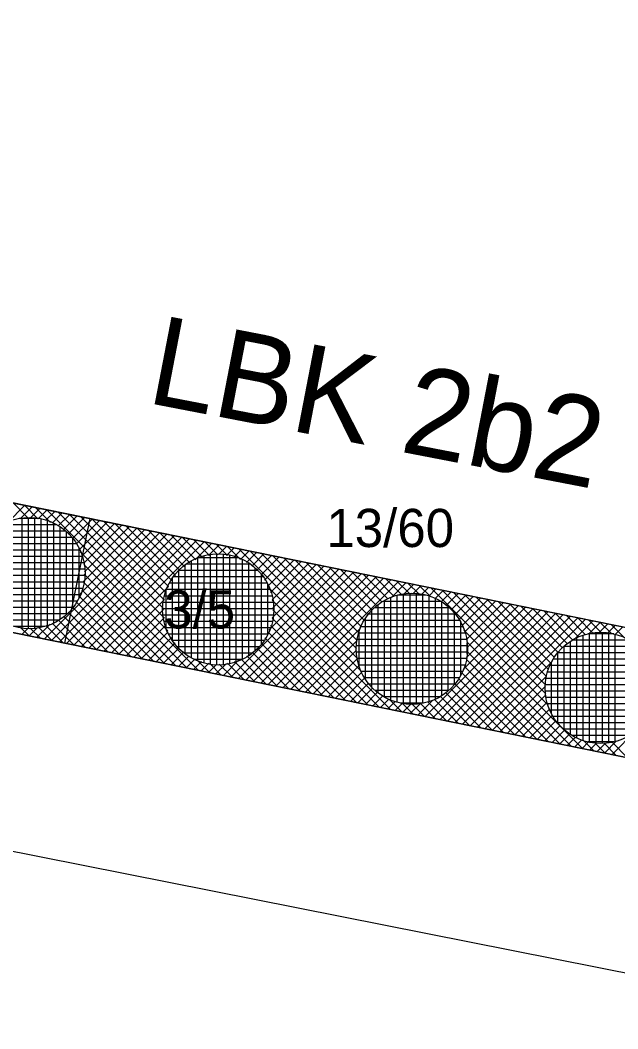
# Model space of a CAD drawing. Extents: x -566461 to -565198, y -1096301 to -1095707.
# Drawn here: x -565776.63 to -565757.83, y -1096136.49 to -1096104.77 of the extents above; entities that cross this region are included whole.
import ezdxf

# ---------------------------------------------------------------- set-up
doc = ezdxf.new("R2010")
doc.units = 0
for name, color, linetype in [('Vrstva 1', 7, 'Continuous'), ('Vrstva 40', 7, 'Continuous'), ('Vrstva 41', 7, 'Continuous'), ('Vrstva 42', 7, 'Continuous'), ('Vrstva 44', 7, 'Continuous')]:
    doc.layers.add(name, color=color, linetype=linetype)

msp = doc.modelspace()

# ---------------------------------------------------------------- linework, layer by layer
at = {"layer": 'Vrstva 1'}
for p, q in [((-565849.04, -1096105.26), (-565748.22, -1096125.78)), ((-565697.28, -1096140.23), (-565854, -1096108.33)), ((-565855.22, -1096115.35), (-565699.29, -1096146.31))]:
    msp.add_line(p, q, dxfattribs=at)
at = {"layer": 'Vrstva 41'}
for p, q in [((-565776.853, -1096119.953), (-565776.375, -1096120.432)), ((-565777.029, -1096120.574), (-565776.483, -1096120.028)), ((-565776.628, -1096120.456), (-565776.248, -1096120.076)), ((-565776.498, -1096120.025), (-565776.07, -1096120.453)), ((-565776.32, -1096120.431), (-565776.013, -1096120.124)), ((-565776.143, -1096120.098), (-565775.676, -1096120.565)), ((-565776.061, -1096120.455), (-565775.778, -1096120.172)), ((-565775.831, -1096120.508), (-565775.543, -1096120.22)), ((-565775.788, -1096120.17), (-565771.982, -1096123.976)), ((-565775.626, -1096120.585), (-565775.308, -1096120.268)), ((-565775.433, -1096120.242), (-565772.096, -1096123.579)), ((-565775.441, -1096120.684), (-565775.073, -1096120.315)), ((-565775.274, -1096120.799), (-565774.838, -1096120.363)), ((-565775.124, -1096120.932), (-565774.603, -1096120.411)), ((-565775.078, -1096120.314), (-565772.12, -1096123.273)), ((-565774.99, -1096121.081), (-565774.368, -1096120.459)), ((-565774.873, -1096121.247), (-565774.133, -1096120.507)), ((-565774.773, -1096121.43), (-565773.898, -1096120.555)), ((-565774.723, -1096120.387), (-565772.095, -1096123.014)), ((-565774.367, -1096120.459), (-565772.042, -1096122.785)), ((-565774.012, -1096120.531), (-565771.963, -1096122.581)), ((-565775.878, -1096124.232), (-565772.488, -1096120.842)), ((-565775.643, -1096124.279), (-565772.253, -1096120.889)), ((-565774.739, -1096122.81), (-565772.723, -1096120.794)), ((-565774.693, -1096121.632), (-565773.663, -1096120.602)), ((-565774.638, -1096121.86), (-565773.428, -1096120.65)), ((-565774.638, -1096122.426), (-565772.958, -1096120.746)), ((-565774.612, -1096122.117), (-565773.193, -1096120.698)), ((-565773.657, -1096120.604), (-565771.864, -1096122.397)), ((-565773.302, -1096120.676), (-565771.747, -1096122.231)), ((-565772.947, -1096120.748), (-565771.613, -1096122.082)), ((-565772.592, -1096120.82), (-565771.463, -1096121.949)), ((-565772.237, -1096120.893), (-565771.297, -1096121.832)), ((-565775.408, -1096124.327), (-565772.018, -1096120.937)), ((-565775.173, -1096124.375), (-565771.783, -1096120.985)), ((-565774.938, -1096124.423), (-565771.548, -1096121.033)), ((-565774.703, -1096124.471), (-565771.313, -1096121.081)), ((-565774.468, -1096124.519), (-565771.078, -1096121.129)), ((-565774.233, -1096124.566), (-565770.843, -1096121.176)), ((-565771.882, -1096120.965), (-565771.113, -1096121.734)), ((-565771.526, -1096121.037), (-565770.907, -1096121.656)), ((-565771.171, -1096121.11), (-565770.678, -1096121.603)), ((-565770.816, -1096121.182), (-565770.418, -1096121.58)), ((-565774.745, -1096121.496), (-565771.02, -1096125.22)), ((-565771.122, -1096121.738), (-565770.608, -1096121.224)), ((-565770.709, -1096121.608), (-565770.373, -1096121.272)), ((-565770.461, -1096121.254), (-565770.11, -1096121.605)), ((-565770.397, -1096121.579), (-565770.138, -1096121.32)), ((-565770.136, -1096121.601), (-565769.903, -1096121.368)), ((-565770.106, -1096121.326), (-565769.709, -1096121.724)), ((-565769.905, -1096121.653), (-565769.668, -1096121.416)), ((-565769.751, -1096121.399), (-565765.898, -1096125.251)), ((-565769.698, -1096121.728), (-565769.433, -1096121.463)), ((-565769.513, -1096121.826), (-565769.198, -1096121.511)), ((-565769.396, -1096121.471), (-565766.021, -1096124.846)), ((-565769.345, -1096121.942), (-565768.963, -1096121.559)), ((-565769.195, -1096122.074), (-565768.728, -1096121.607)), ((-565769.06, -1096122.222), (-565768.493, -1096121.655)), ((-565769.041, -1096121.543), (-565766.05, -1096124.534)), ((-565768.943, -1096122.387), (-565768.258, -1096121.703)), ((-565768.842, -1096122.57), (-565768.023, -1096121.75)), ((-565768.762, -1096122.772), (-565767.788, -1096121.798)), ((-565768.707, -1096123), (-565767.553, -1096121.846)), ((-565768.685, -1096121.616), (-565766.027, -1096124.274)), ((-565768.33, -1096121.688), (-565765.976, -1096124.042)), ((-565767.975, -1096121.76), (-565765.901, -1096123.834)), ((-565767.62, -1096121.832), (-565765.803, -1096123.649)), ((-565774.633, -1096121.89), (-565771.376, -1096125.148)), ((-565770.003, -1096125.427), (-565766.613, -1096122.037)), ((-565769.768, -1096125.475), (-565766.378, -1096122.085)), ((-565769.533, -1096125.523), (-565766.143, -1096122.133)), ((-565768.808, -1096123.95), (-565766.848, -1096121.99)), ((-565768.706, -1096123.565), (-565767.083, -1096121.942)), ((-565768.681, -1096123.257), (-565767.318, -1096121.894)), ((-565767.265, -1096121.905), (-565765.689, -1096123.481)), ((-565766.91, -1096121.977), (-565765.557, -1096123.33)), ((-565766.555, -1096122.049), (-565765.41, -1096123.194)), ((-565766.2, -1096122.122), (-565765.246, -1096123.075)), ((-565774.64, -1096122.449), (-565772.086, -1096125.003)), ((-565774.613, -1096122.193), (-565771.731, -1096125.076)), ((-565769.298, -1096125.571), (-565765.908, -1096122.181)), ((-565769.063, -1096125.619), (-565765.673, -1096122.229)), ((-565768.828, -1096125.667), (-565765.438, -1096122.277)), ((-565768.593, -1096125.714), (-565765.203, -1096122.324)), ((-565768.358, -1096125.762), (-565764.968, -1096122.372)), ((-565768.123, -1096125.81), (-565764.733, -1096122.42)), ((-565765.844, -1096122.194), (-565765.064, -1096122.974)), ((-565765.489, -1096122.266), (-565764.864, -1096122.891)), ((-565765.134, -1096122.338), (-565764.64, -1096122.833)), ((-565764.956, -1096122.926), (-565764.498, -1096122.468)), ((-565764.779, -1096122.411), (-565764.386, -1096122.804)), ((-565764.424, -1096122.483), (-565764.092, -1096122.815)), ((-565774.691, -1096122.681), (-565772.441, -1096124.931)), ((-565773.998, -1096124.614), (-565771.962, -1096122.578)), ((-565768.824, -1096122.609), (-565764.983, -1096126.449)), ((-565764.568, -1096122.821), (-565764.263, -1096122.516)), ((-565764.266, -1096122.802), (-565764.028, -1096122.564)), ((-565764.069, -1096122.555), (-565763.719, -1096122.905)), ((-565764.009, -1096122.828), (-565763.793, -1096122.611)), ((-565763.781, -1096122.883), (-565763.558, -1096122.659)), ((-565763.714, -1096122.628), (-565760.025, -1096126.316)), ((-565763.578, -1096122.962), (-565763.323, -1096122.707)), ((-565763.395, -1096123.062), (-565763.088, -1096122.755)), ((-565763.359, -1096122.7), (-565760.102, -1096125.956)), ((-565763.229, -1096123.179), (-565762.853, -1096122.803)), ((-565763.003, -1096122.772), (-565760.107, -1096125.668)), ((-565774.87, -1096123.068), (-565773.151, -1096124.787)), ((-565774.77, -1096122.885), (-565772.796, -1096124.859)), ((-565773.763, -1096124.662), (-565772.092, -1096122.991)), ((-565768.705, -1096123.01), (-565765.338, -1096126.377)), ((-565763.08, -1096123.313), (-565762.618, -1096122.851)), ((-565762.947, -1096123.462), (-565762.383, -1096122.898)), ((-565762.83, -1096123.629), (-565762.148, -1096122.946)), ((-565762.73, -1096123.812), (-565761.913, -1096122.994)), ((-565762.651, -1096124.016), (-565761.678, -1096123.042)), ((-565762.648, -1096122.844), (-565760.076, -1096125.416)), ((-565762.597, -1096124.244), (-565761.443, -1096123.09)), ((-565762.293, -1096122.917), (-565760.014, -1096125.196)), ((-565761.938, -1096122.989), (-565759.929, -1096124.998)), ((-565761.583, -1096123.061), (-565759.826, -1096124.818)), ((-565775.12, -1096123.384), (-565773.861, -1096124.642)), ((-565774.986, -1096123.234), (-565773.506, -1096124.714)), ((-565773.528, -1096124.71), (-565772.121, -1096123.303)), ((-565768.681, -1096123.317), (-565765.694, -1096126.305)), ((-565763.893, -1096126.671), (-565760.503, -1096123.281)), ((-565763.658, -1096126.719), (-565760.268, -1096123.329)), ((-565763.423, -1096126.767), (-565760.033, -1096123.377)), ((-565763.188, -1096126.815), (-565759.798, -1096123.425)), ((-565762.7, -1096125.196), (-565760.738, -1096123.233)), ((-565762.598, -1096124.811), (-565760.973, -1096123.185)), ((-565762.572, -1096124.502), (-565761.208, -1096123.138)), ((-565761.228, -1096123.134), (-565759.706, -1096124.655)), ((-565760.873, -1096123.206), (-565759.57, -1096124.509)), ((-565760.518, -1096123.278), (-565759.417, -1096124.379)), ((-565760.162, -1096123.35), (-565759.248, -1096124.265)), ((-565759.807, -1096123.423), (-565759.06, -1096124.17)), ((-565775.62, -1096123.732), (-565774.927, -1096124.425)), ((-565775.436, -1096123.633), (-565774.572, -1096124.497)), ((-565775.27, -1096123.517), (-565774.217, -1096124.57)), ((-565773.293, -1096124.758), (-565772.099, -1096123.564)), ((-565768.707, -1096123.574), (-565766.049, -1096126.232)), ((-565762.953, -1096126.862), (-565759.563, -1096123.472)), ((-565762.718, -1096126.91), (-565759.328, -1096123.52)), ((-565762.483, -1096126.958), (-565759.093, -1096123.568)), ((-565762.248, -1096127.006), (-565758.858, -1096123.616)), ((-565759.452, -1096123.495), (-565758.851, -1096124.097)), ((-565759.197, -1096124.239), (-565758.623, -1096123.664)), ((-565759.097, -1096123.567), (-565758.617, -1096124.047)), ((-565758.744, -1096124.068), (-565758.388, -1096123.712)), ((-565758.742, -1096123.64), (-565758.354, -1096124.028)), ((-565758.387, -1096123.712), (-565758.038, -1096124.06)), ((-565776.618, -1096123.865), (-565776.347, -1096124.136)), ((-565776.583, -1096124.088), (-565776.383, -1096123.888)), ((-565776.348, -1096124.136), (-565776.08, -1096123.868)), ((-565776.312, -1096123.889), (-565775.992, -1096124.208)), ((-565776.113, -1096124.184), (-565775.69, -1096123.761)), ((-565776.054, -1096123.864), (-565775.637, -1096124.281)), ((-565775.825, -1096123.81), (-565775.282, -1096124.353)), ((-565773.058, -1096124.806), (-565772.047, -1096123.795)), ((-565772.823, -1096124.853), (-565771.972, -1096124.002)), ((-565768.834, -1096124.013), (-565766.759, -1096126.088)), ((-565768.756, -1096123.807), (-565766.404, -1096126.16)), ((-565767.888, -1096125.858), (-565765.924, -1096123.894)), ((-565762.675, -1096123.949), (-565758.946, -1096127.678)), ((-565758.423, -1096124.03), (-565758.153, -1096123.759)), ((-565758.153, -1096124.042), (-565757.917, -1096123.807)), ((-565758.032, -1096123.784), (-565757.613, -1096124.202)), ((-565757.917, -1096124.089), (-565757.682, -1096123.855)), ((-565772.588, -1096124.901), (-565771.874, -1096124.187)), ((-565772.353, -1096124.949), (-565771.758, -1096124.355)), ((-565769.049, -1096124.363), (-565767.469, -1096125.943)), ((-565768.932, -1096124.197), (-565767.114, -1096126.015)), ((-565767.653, -1096125.906), (-565766.029, -1096124.282)), ((-565762.585, -1096124.322), (-565759.301, -1096127.606)), ((-565772.118, -1096124.997), (-565771.626, -1096124.505)), ((-565771.883, -1096125.045), (-565771.478, -1096124.64)), ((-565769.331, -1096124.647), (-565768.179, -1096125.799)), ((-565769.182, -1096124.513), (-565767.824, -1096125.871)), ((-565767.418, -1096125.954), (-565766.048, -1096124.584)), ((-565762.578, -1096124.612), (-565759.656, -1096127.533)), ((-565771.648, -1096125.093), (-565771.313, -1096124.757)), ((-565771.413, -1096125.14), (-565771.13, -1096124.858)), ((-565771.178, -1096125.188), (-565770.928, -1096124.938)), ((-565771.076, -1096124.882), (-565770.665, -1096125.293)), ((-565770.943, -1096125.236), (-565770.7, -1096124.993)), ((-565770.708, -1096125.284), (-565770.443, -1096125.019)), ((-565770.679, -1096124.996), (-565770.31, -1096125.365)), ((-565770.473, -1096125.332), (-565770.141, -1096124.999)), ((-565770.373, -1096125.02), (-565769.955, -1096125.437)), ((-565770.238, -1096125.38), (-565769.75, -1096124.892)), ((-565770.114, -1096124.995), (-565769.6, -1096125.509)), ((-565769.885, -1096124.942), (-565769.245, -1096125.582)), ((-565769.681, -1096124.863), (-565768.89, -1096125.654)), ((-565769.497, -1096124.764), (-565768.535, -1096125.726)), ((-565767.183, -1096126.001), (-565766.022, -1096124.841)), ((-565762.604, -1096124.868), (-565760.011, -1096127.461)), ((-565762.013, -1096127.054), (-565759.901, -1096124.943)), ((-565766.948, -1096126.049), (-565765.967, -1096125.069)), ((-565766.713, -1096126.097), (-565765.888, -1096125.272)), ((-565762.744, -1096125.294), (-565760.722, -1096127.317)), ((-565762.661, -1096125.094), (-565760.367, -1096127.389)), ((-565766.478, -1096126.145), (-565765.788, -1096125.455)), ((-565766.243, -1096126.193), (-565765.671, -1096125.621)), ((-565762.964, -1096125.64), (-565761.432, -1096127.172)), ((-565762.845, -1096125.476), (-565761.077, -1096127.244)), ((-565761.778, -1096127.102), (-565760.072, -1096125.396)), ((-565766.008, -1096126.241), (-565765.537, -1096125.77)), ((-565765.773, -1096126.288), (-565765.388, -1096125.903)), ((-565763.251, -1096125.919), (-565762.142, -1096127.027)), ((-565763.1, -1096125.787), (-565761.787, -1096127.1)), ((-565761.543, -1096127.15), (-565760.11, -1096125.717)), ((-565765.538, -1096126.336), (-565765.221, -1096126.02)), ((-565765.303, -1096126.384), (-565765.038, -1096126.12)), ((-565765.068, -1096126.432), (-565764.834, -1096126.199)), ((-565765.021, -1096126.128), (-565764.628, -1096126.521)), ((-565764.833, -1096126.48), (-565764.606, -1096126.253)), ((-565764.616, -1096126.251), (-565764.273, -1096126.594)), ((-565764.598, -1096126.528), (-565764.348, -1096126.278)), ((-565764.363, -1096126.575), (-565764.045, -1096126.258)), ((-565764.304, -1096126.28), (-565763.918, -1096126.666)), ((-565764.128, -1096126.623), (-565763.654, -1096126.15)), ((-565764.044, -1096126.257), (-565763.563, -1096126.738)), ((-565763.812, -1096126.206), (-565763.208, -1096126.811)), ((-565763.604, -1096126.131), (-565762.853, -1096126.883)), ((-565763.419, -1096126.033), (-565762.497, -1096126.955)), ((-565761.308, -1096127.197), (-565760.098, -1096125.987)), ((-565761.073, -1096127.245), (-565760.051, -1096126.223)), ((-565760.838, -1096127.293), (-565759.979, -1096126.435)), ((-565760.602, -1096127.341), (-565759.887, -1096126.625)), ((-565760.367, -1096127.389), (-565759.777, -1096126.798)), ((-565760.132, -1096127.437), (-565759.648, -1096126.953)), ((-565759.897, -1096127.484), (-565759.504, -1096127.091)), ((-565759.662, -1096127.532), (-565759.343, -1096127.213)), ((-565758.017, -1096127.867), (-565757.264, -1096127.113)), ((-565759.427, -1096127.58), (-565759.165, -1096127.318)), ((-565759.192, -1096127.628), (-565758.969, -1096127.405)), ((-565758.957, -1096127.676), (-565758.752, -1096127.47)), ((-565758.916, -1096127.425), (-565758.591, -1096127.75)), ((-565758.722, -1096127.724), (-565758.505, -1096127.506)), ((-565758.556, -1096127.502), (-565758.236, -1096127.823)), ((-565758.487, -1096127.771), (-565758.221, -1096127.505)), ((-565758.268, -1096127.507), (-565757.881, -1096127.895)), ((-565758.252, -1096127.819), (-565757.872, -1096127.439)), ((-565758.016, -1096127.476), (-565757.526, -1096127.967))]:
    msp.add_line(p, q, dxfattribs=at)
at = {"layer": 'Vrstva 42'}
msp.add_line((-565774.442, -1096120.443), (-565775.24, -1096124.361), dxfattribs=at)
msp.add_lwpolyline([(-565828.2, -1096027.12), (-565826.72, -1096023.51), (-565829.55, -1096025.32), (-565832.07, -1096026.09), (-565854, -1096108.33), (-565697.28, -1096140.23), (-565696.05, -1096136.4), (-565849.04, -1096105.26)], close=True, dxfattribs=at)
at = {"layer": 'Vrstva 44'}
for p, q in [((-565776.026, -1096120.44), (-565776.66, -1096120.44)), ((-565776.57, -1096123.894), (-565776.57, -1096120.427)), ((-565776.37, -1096123.909), (-565776.37, -1096120.412)), ((-565776.17, -1096123.9), (-565776.17, -1096120.419)), ((-565775.97, -1096123.868), (-565775.97, -1096120.45)), ((-565775.77, -1096123.813), (-565775.77, -1096120.507)), ((-565775.194, -1096120.84), (-565777.486, -1096120.84)), ((-565775.476, -1096120.64), (-565777.203, -1096120.64)), ((-565775.57, -1096123.731), (-565775.57, -1096120.591)), ((-565775.37, -1096123.614), (-565775.37, -1096120.703)), ((-565775.17, -1096123.461), (-565775.17, -1096120.861)), ((-565774.996, -1096121.04), (-565777.682, -1096121.04)), ((-565774.97, -1096123.246), (-565774.97, -1096121.074)), ((-565774.746, -1096121.44), (-565777.934, -1096121.44)), ((-565774.854, -1096121.24), (-565777.827, -1096121.24)), ((-565774.77, -1096122.932), (-565774.77, -1096121.391)), ((-565774.621, -1096121.84), (-565778.059, -1096121.84)), ((-565774.67, -1096121.64), (-565778.009, -1096121.64)), ((-565771.24, -1096124.834), (-565771.24, -1096121.767)), ((-565769.74, -1096121.68), (-565771.059, -1096121.68)), ((-565771.04, -1096124.928), (-565771.04, -1096121.672)), ((-565770.84, -1096124.993), (-565770.84, -1096121.608)), ((-565770.64, -1096125.032), (-565770.64, -1096121.568)), ((-565770.44, -1096125.049), (-565770.44, -1096121.552)), ((-565770.24, -1096125.041), (-565770.24, -1096121.559)), ((-565770.04, -1096125.011), (-565770.04, -1096121.588)), ((-565769.84, -1096124.956), (-565769.84, -1096121.644)), ((-565769.64, -1096124.876), (-565769.64, -1096121.726)), ((-565769.44, -1096124.761), (-565769.44, -1096121.837)), ((-565774.596, -1096122.04), (-565778.085, -1096122.04)), ((-565769.147, -1096122.08), (-565771.652, -1096122.08)), ((-565771.64, -1096124.533), (-565771.64, -1096122.068)), ((-565771.44, -1096124.705), (-565771.44, -1096121.894)), ((-565769.38, -1096121.88), (-565771.42, -1096121.88)), ((-565769.24, -1096124.609), (-565769.24, -1096121.992)), ((-565774.593, -1096122.24), (-565778.088, -1096122.24)), ((-565774.613, -1096122.44), (-565778.066, -1096122.44)), ((-565768.855, -1096122.48), (-565771.944, -1096122.48)), ((-565771.84, -1096124.293), (-565771.84, -1096122.308)), ((-565768.98, -1096122.28), (-565771.821, -1096122.28)), ((-565769.04, -1096124.398), (-565769.04, -1096122.2)), ((-565774.658, -1096122.64), (-565778.021, -1096122.64)), ((-565772.04, -1096123.906), (-565772.04, -1096122.692)), ((-565768.766, -1096122.68), (-565772.035, -1096122.68)), ((-565768.84, -1096124.09), (-565768.84, -1096122.511)), ((-565764.37, -1096126.288), (-565764.37, -1096122.793)), ((-565764.17, -1096126.283), (-565764.17, -1096122.797)), ((-565774.73, -1096122.84), (-565777.951, -1096122.84)), ((-565774.829, -1096123.04), (-565777.852, -1096123.04)), ((-565768.664, -1096123.08), (-565772.135, -1096123.08)), ((-565768.703, -1096122.88), (-565772.099, -1096122.88)), ((-565763.396, -1096123.05), (-565765.227, -1096123.05)), ((-565765.17, -1096126.062), (-565765.17, -1096123.018)), ((-565764.97, -1096126.16), (-565764.97, -1096122.921)), ((-565764.77, -1096126.228), (-565764.77, -1096122.852)), ((-565763.863, -1096122.85), (-565764.761, -1096122.85)), ((-565764.57, -1096126.269), (-565764.57, -1096122.811)), ((-565763.97, -1096126.255), (-565763.97, -1096122.824)), ((-565763.77, -1096126.203), (-565763.77, -1096122.876)), ((-565763.57, -1096126.125), (-565763.57, -1096122.956)), ((-565763.37, -1096126.014), (-565763.37, -1096123.065)), ((-565774.965, -1096123.24), (-565777.714, -1096123.24)), ((-565775.148, -1096123.44), (-565777.532, -1096123.44)), ((-565768.651, -1096123.28), (-565772.148, -1096123.28)), ((-565765.57, -1096125.752), (-565765.57, -1096123.328)), ((-565763.13, -1096123.25), (-565765.491, -1096123.25)), ((-565765.37, -1096125.931), (-565765.37, -1096123.148)), ((-565763.17, -1096125.866), (-565763.17, -1096123.214)), ((-565762.97, -1096125.663), (-565762.97, -1096123.415)), ((-565775.408, -1096123.64), (-565777.272, -1096123.64)), ((-565768.661, -1096123.48), (-565772.139, -1096123.48)), ((-565768.694, -1096123.68), (-565772.107, -1096123.68)), ((-565762.805, -1096123.65), (-565765.817, -1096123.65)), ((-565765.77, -1096125.502), (-565765.77, -1096123.579)), ((-565762.943, -1096123.45), (-565765.677, -1096123.45)), ((-565762.77, -1096125.367), (-565762.77, -1096123.71)), ((-565775.855, -1096123.84), (-565776.829, -1096123.84)), ((-565768.75, -1096123.88), (-565772.05, -1096123.88)), ((-565762.632, -1096124.05), (-565765.988, -1096124.05)), ((-565765.97, -1096125.092), (-565765.97, -1096123.991)), ((-565762.702, -1096123.85), (-565765.916, -1096123.85)), ((-565757.962, -1096124.07), (-565758.777, -1096124.07)), ((-565758.72, -1096127.483), (-565758.72, -1096124.057)), ((-565758.52, -1096127.512), (-565758.52, -1096124.027)), ((-565758.32, -1096127.517), (-565758.32, -1096124.022)), ((-565758.12, -1096127.501), (-565758.12, -1096124.04)), ((-565768.834, -1096124.08), (-565771.964, -1096124.08)), ((-565768.953, -1096124.28), (-565771.848, -1096124.28)), ((-565762.586, -1096124.25), (-565766.035, -1096124.25)), ((-565762.57, -1096124.71), (-565762.57, -1096124.368)), ((-565759.32, -1096127.24), (-565759.32, -1096124.302)), ((-565757.472, -1096124.27), (-565759.269, -1096124.27)), ((-565759.12, -1096127.349), (-565759.12, -1096124.19)), ((-565758.92, -1096127.429), (-565758.92, -1096124.111)), ((-565757.92, -1096127.461), (-565757.92, -1096124.081)), ((-565769.108, -1096124.48), (-565771.69, -1096124.48)), ((-565769.326, -1096124.68), (-565771.475, -1096124.68)), ((-565762.564, -1096124.45), (-565766.057, -1096124.45)), ((-565762.564, -1096124.65), (-565766.055, -1096124.65)), ((-565757.01, -1096124.67), (-565759.729, -1096124.67)), ((-565759.72, -1096126.881), (-565759.72, -1096124.659)), ((-565757.201, -1096124.47), (-565759.54, -1096124.47)), ((-565759.52, -1096127.086), (-565759.52, -1096124.453)), ((-565769.649, -1096124.88), (-565771.148, -1096124.88)), ((-565762.589, -1096124.85), (-565766.03, -1096124.85)), ((-565759.92, -1096126.578), (-565759.92, -1096124.962)), ((-565756.871, -1096124.87), (-565759.87, -1096124.87)), ((-565762.638, -1096125.05), (-565765.982, -1096125.05)), ((-565762.712, -1096125.25), (-565765.909, -1096125.25)), ((-565756.694, -1096125.27), (-565760.045, -1096125.27)), ((-565756.766, -1096125.07), (-565759.972, -1096125.07)), ((-565762.815, -1096125.45), (-565765.803, -1096125.45)), ((-565762.96, -1096125.65), (-565765.661, -1096125.65)), ((-565756.648, -1096125.47), (-565760.093, -1096125.47)), ((-565763.151, -1096125.85), (-565765.467, -1096125.85)), ((-565756.625, -1096125.67), (-565760.117, -1096125.67)), ((-565756.624, -1096125.87), (-565760.116, -1096125.87)), ((-565763.428, -1096126.05), (-565765.191, -1096126.05)), ((-565763.947, -1096126.25), (-565764.68, -1096126.25)), ((-565756.647, -1096126.07), (-565760.092, -1096126.07)), ((-565756.695, -1096126.27), (-565760.045, -1096126.27)), ((-565756.768, -1096126.47), (-565759.973, -1096126.47)), ((-565756.87, -1096126.67), (-565759.869, -1096126.67)), ((-565757.011, -1096126.87), (-565759.729, -1096126.87)), ((-565757.199, -1096127.07), (-565759.539, -1096127.07)), ((-565757.469, -1096127.27), (-565759.268, -1096127.27)), ((-565757.961, -1096127.47), (-565758.782, -1096127.47))]:
    msp.add_line(p, q, dxfattribs=at)
for centre in [(-565776.34, -1096122.16), (-565770.4, -1096123.3), (-565764.31, -1096124.54), (-565758.37, -1096125.77)]:
    msp.add_circle(centre, 1.75, dxfattribs=at)

# ---------------------------------------------------------------- texts
at = {"layer": 'Vrstva 1'}
msp.add_text('LBK 2b2', height=2.8, rotation=349.0833, dxfattribs=at).set_placement((-565772.704, -1096116.794))
at = {"layer": 'Vrstva 40'}
for s, p in [('13/60', (-565767, -1096121.34)), ('3/5', (-565772.1, -1096123.9))]:
    msp.add_text(s, height=1.2, dxfattribs=at).set_placement(p)

doc.saveas('drawing.dxf')
